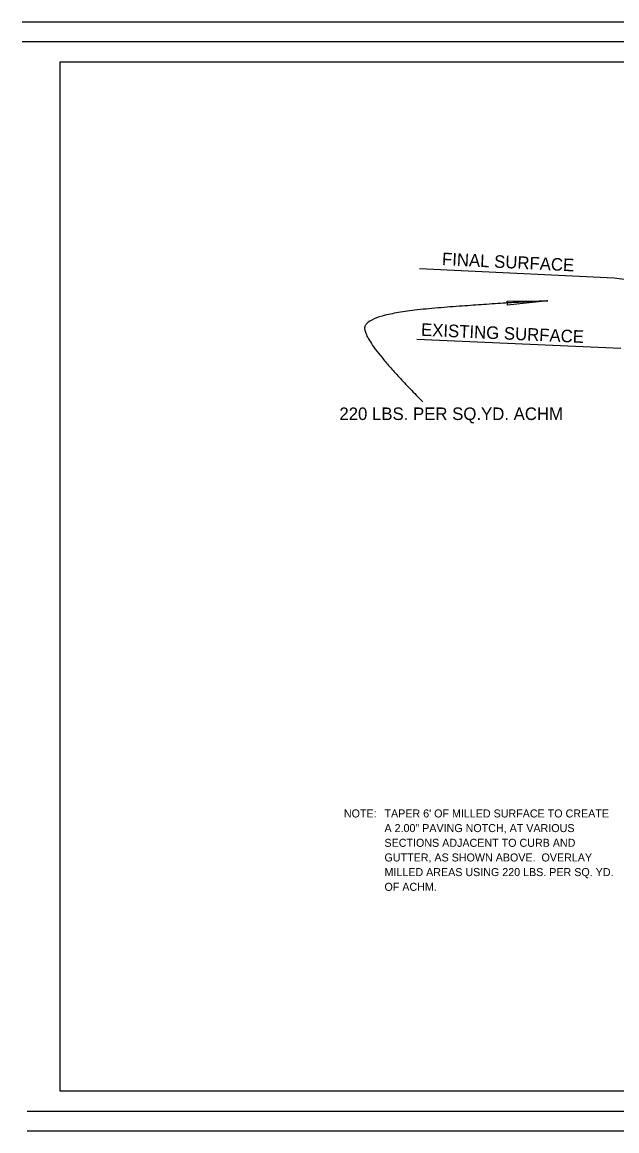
# Model space of a CAD drawing. Extents: x 1944905 to 1956777, y 763871 to 764977.
# Drawn here: x 1955158 to 1955751, y 763871 to 764977 of the extents above; entities that cross this region are included whole.
import ezdxf

# ---------------------------------------------------------------- set-up
doc = ezdxf.new("R2010")
doc.units = 0
doc.layers.add('Default', color=7, linetype='Continuous')
doc.layers.add('R_Dimension', color=7, linetype='Continuous')

msp = doc.modelspace()

# ---------------------------------------------------------------- linework, layer by layer
at = {"layer": 'Default'}
for p, q in [((1956776.6, 764976.7), (1955157.9, 764976.7)), ((1956776.6, 764957), (1955157.9, 764957)), ((1955195.7, 764937.3), (1956776.6, 764937.3)), ((1955195.7, 763910.1), (1955195.7, 764937.3)), ((1956776.6, 763910.1), (1955195.7, 763910.1)), ((1955162.8, 763890.4), (1956776.6, 763890.4)), ((1955162.8, 763870.7), (1956776.6, 763870.7))]:
    msp.add_line(p, q, dxfattribs=at)
at = {"layer": 'R_Dimension'}
for p, q in [((1955554.2, 764731.1), (1955748.3, 764721.7)), ((1955748.3, 764721.7), (1956247.9, 764651.5)), ((1955641.5, 764698.3), (1955682.2, 764698.6)), ((1955641.8, 764694.3), (1955641.5, 764698.3)), ((1955682.2, 764698.6), (1955641.8, 764694.3)), ((1955551.5, 764660.6), (1955754.9, 764651.5))]:
    msp.add_line(p, q, dxfattribs=at)
msp.add_open_spline([(1955682.2, 764698.6), (1955641.6, 764697.1), (1955502.1, 764686), (1955496.9, 764659), (1955557.3, 764598.1)], degree=2, dxfattribs=at)

# ---------------------------------------------------------------- texts
for s, rotation, p in [('FINAL SURFACE', 357.2336, (1955576.3, 764734.4)), ('EXISTING SURFACE', 357.4408, (1955555.4, 764663.9))]:
    msp.add_text(s, height=12.504, rotation=rotation, dxfattribs=at).set_placement(p)
for s, height, p in [('220 LBS. PER SQ.YD. ACHM', 12.504, (1955474.2, 764579.8)), ('NOTE: ', 7.98, (1955478.7, 764183.3)), ("TAPER 6' OF MILLED SURFACE TO CREATE", 7.982, (1955519.2, 764183.3)), ('A 2.00" PAVING NOTCH, AT VARIOUS', 7.982, (1955519.2, 764168.7)), ('SECTIONS ADJACENT TO CURB AND', 7.982, (1955519.2, 764154)), ('GUTTER, AS SHOWN ABOVE.  OVERLAY', 7.982, (1955519.2, 764139.4)), ('MILLED AREAS USING 220 LBS. PER SQ. YD.', 7.982, (1955519.2, 764124.8)), ('OF ACHM.', 7.98, (1955519.2, 764110.1))]:
    msp.add_text(s, height=height, dxfattribs=at).set_placement(p)

doc.saveas('drawing.dxf')
